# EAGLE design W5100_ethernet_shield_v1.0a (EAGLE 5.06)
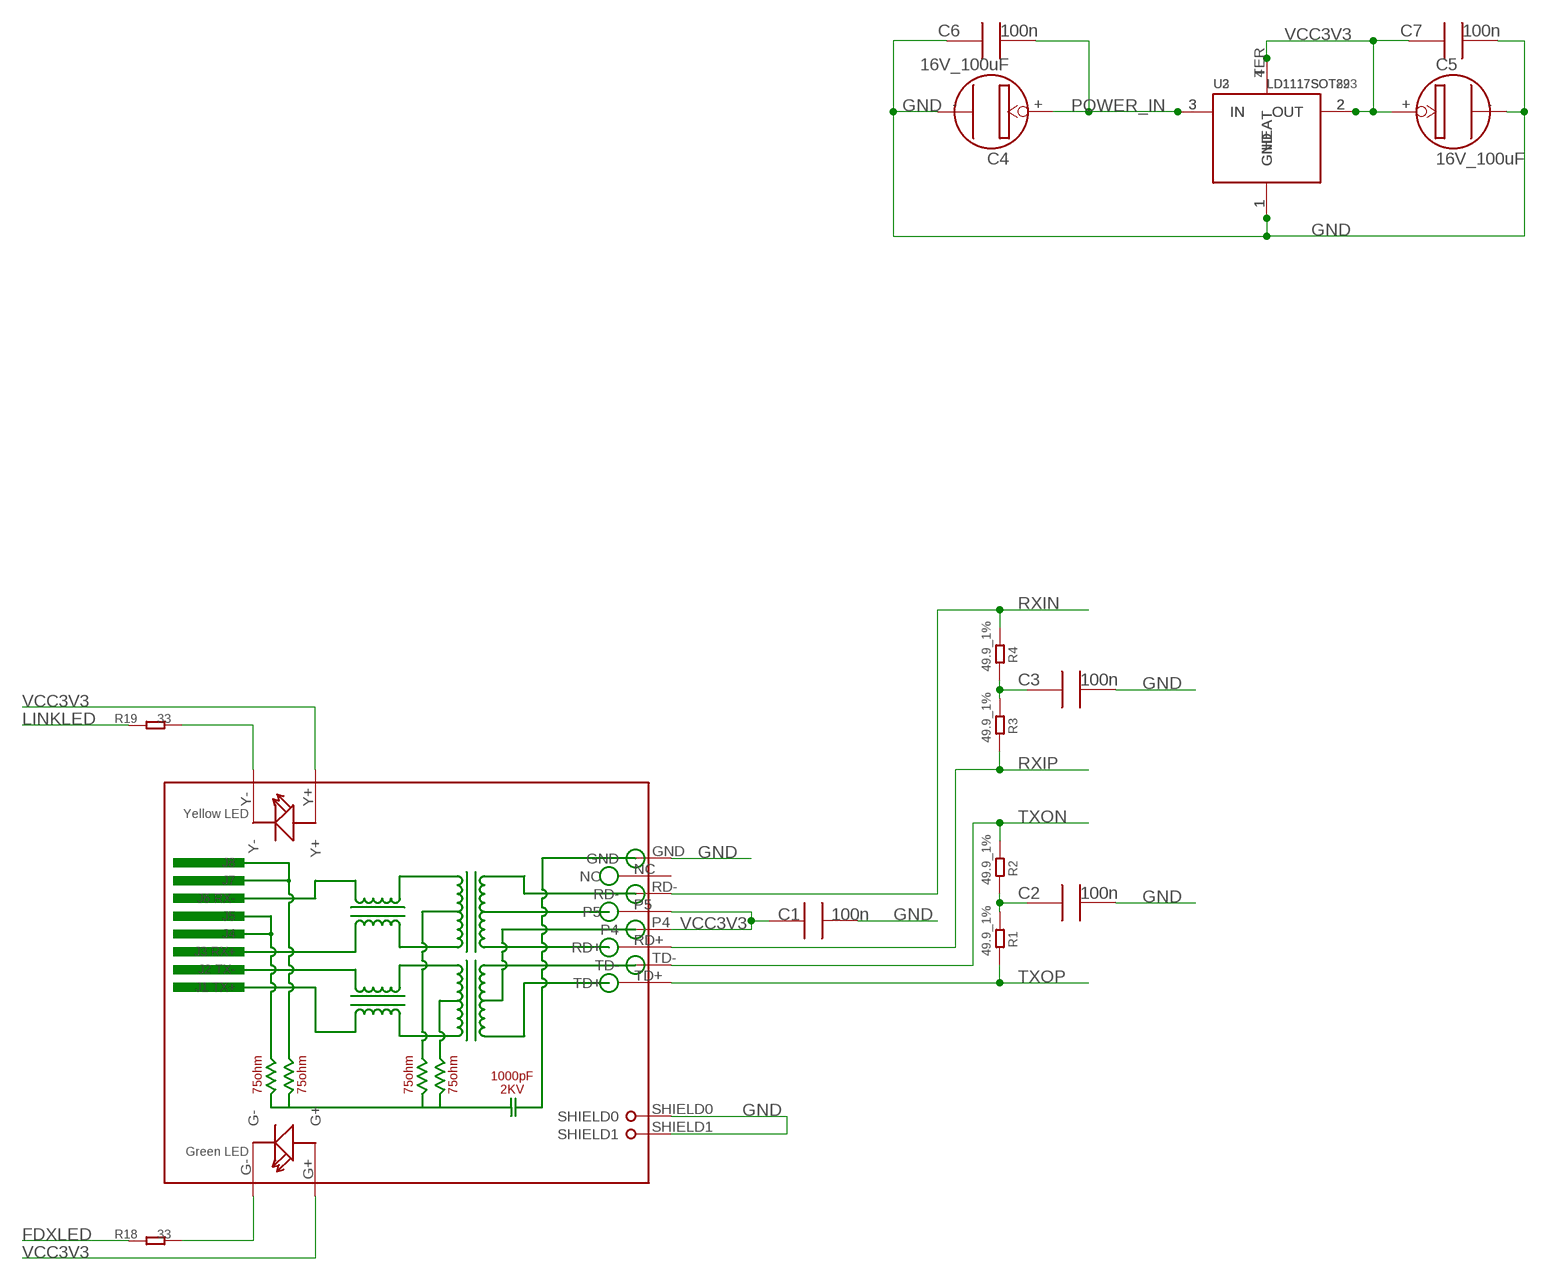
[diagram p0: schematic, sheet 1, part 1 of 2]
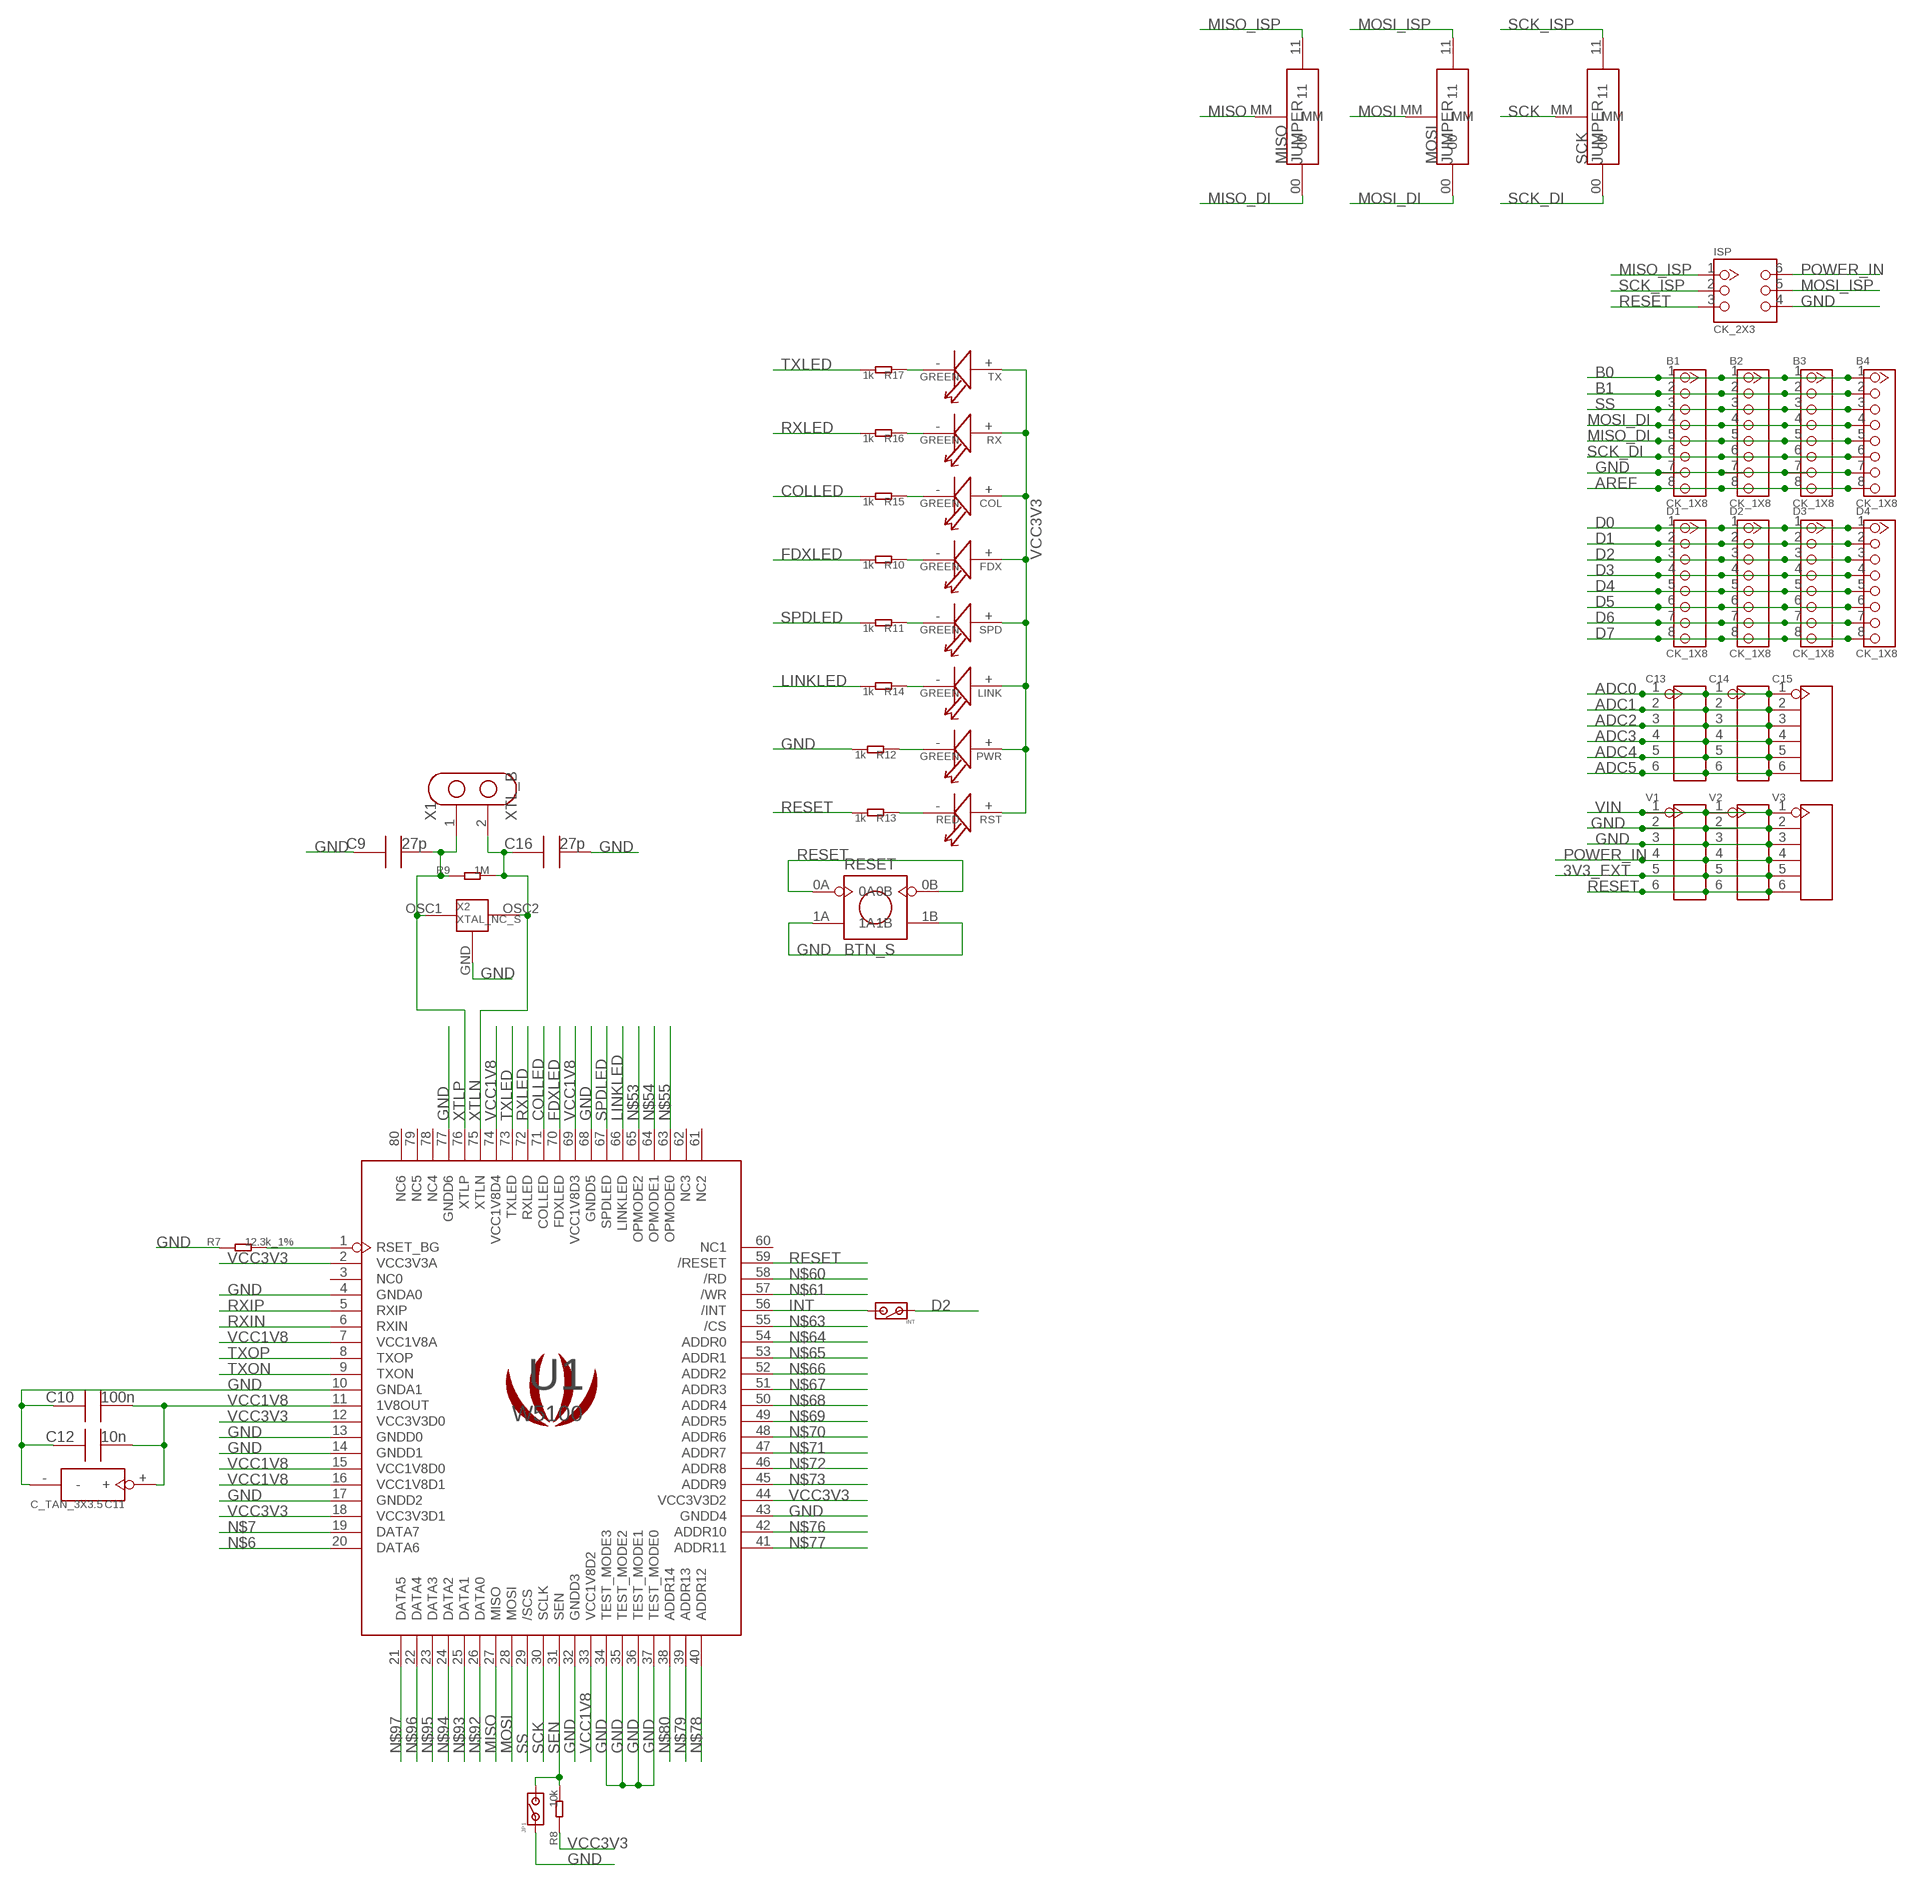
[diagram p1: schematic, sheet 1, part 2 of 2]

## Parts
B1  CK_1X8  CK_1X8DD  [CK_1X8]
B2  CK_1X8  CK_1X8DD  [CK_1X8]
B3  CK_1X8  CK_1X8DD  [CK_1X8]
B4  CK_1X8  CK_1X8DD  [CK_1X8]
C1  100n  C0603  [0603]
C2  100n  C0603  [0603]
C3  100n  C0603  [0603]
C4  16V_100uF  PANASONIC_D260  [SANYO-OSCON_SMD_C6]
C5  16V_100uF  PANASONIC_D260  [SANYO-OSCON_SMD_C6]
C6  100n  C0603  [0603]
C7  100n  C0603  [0603]
C9  27p  C0603  [0603]
C10  100n  C0603  [0603]
C11  C_TAN_3X3.5  [C_TAN_3X3.5]
C12  10n  C0603  [0603]
C13  CK_16  [CK_1*6]
C14  CK_16  [CK_1*6]
C15  CK_16  [CK_1*6]
C16  27p  C0603  [0603]
COL  GREEN  LED0805  [LED0805]
D1  CK_1X8  CK_1X8DD  [CK_1X8]
D2  CK_1X8  CK_1X8DD  [CK_1X8]
D3  CK_1X8  CK_1X8DD  [CK_1X8]
D4  CK_1X8  CK_1X8DD  [CK_1X8]
FDX  GREEN  LED0805  [LED0805]
INT  JP_SW  [JP_SW]
ISP  CK_2X3  [CK_2X3_THIN]
JP1  JP_SW  [JP_SW]
LINK  GREEN  LED0805  [LED0805]
LOGO1  LOGO_COPPER200X166  [LOGO_COPPER]
MISO  JUMPER  [JUMPER]
MOSI  JUMPER  [JUMPER]
PWR  GREEN  LED0805  [LED0805]
R1  49.9_1%  R0603  [0603]
R2  49.9_1%  R0603  [0603]
R3  49.9_1%  R0603  [0603]
R4  49.9_1%  R0603  [0603]
R7  12.3k_1%  R0603  [0603]
R8  10k  R0603  [0603]
R9  1M  R0603  [0603]
R10  1k  R0603  [0603]
R11  1k  R0603  [0603]
R12  1k  R0603  [0603]
R13  1k  R0603  [0603]
R14  1k  R0603  [0603]
R15  1k  R0603  [0603]
R16  1k  R0603  [0603]
R17  1k  R0603  [0603]
R18  33  R0603  [0603]
R19  33  R0603  [0603]
RESET  BTN_S  [BTN_S]
RJ1  HR911105A  [HR911105A]
RST  RED  LED0805  [LED0805]
RX  GREEN  LED0805  [LED0805]
SCK  JUMPER  [JUMPER]
SPD  GREEN  LED0805  [LED0805]
TX  GREEN  LED0805  [LED0805]
U1  W5100  [SQFP80]
U2  LD1117SOT89  [SOT89]
U3  LD1117SOT223  [SOT223]
V1  CK_16  [CK_1*6]
V2  CK_16  [CK_1*6]
V3  CK_16  [CK_1*6]
X1  XTL_B  [XTL_B]
X2  XTAL_NC_S  [XTAL_NC_S]

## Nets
3V3_EXT: V1.5 V2.5 V3.5
ADC0: C13.1 C14.1 C15.1
ADC1: C13.2 C14.2 C15.2
ADC2: C13.3 C14.3 C15.3
ADC3: C13.4 C14.4 C15.4
ADC4: C13.5 C14.5 C15.5
ADC5: C13.6 C14.6 C15.6
AREF: B1.8 B2.8 B3.8 B4.8
B0: B1.1 B2.1 B3.1 B4.1
B1: B1.2 B2.2 B3.2 B4.2
COLLED: R15.2 U1.71(COLLED)
D0: D1.1 D2.1 D3.1 D4.1
D1: D1.2 D2.2 D3.2 D4.2
D2: D1.3 D2.3 D3.3 D4.3 INT.1
D3: D1.4 D2.4 D3.4 D4.4
D4: D1.5 D2.5 D3.5 D4.5
D5: D1.6 D2.6 D3.6 D4.6
D6: D1.7 D2.7 D3.7 D4.7
D7: D1.8 D2.8 D3.8 D4.8
FDXLED: R10.2 R18.1 U1.70(FDXLED)
GND [power]: B1.7 B2.7 B3.7 B4.7 C1.2 C2.2 C3.2 C4.- C5.- C6.1 C7.2 C9.1 C10.1 C11.- C12.1 C16.2 ISP.4 JP1.1 R7.1 R12.2 RESET.1A RESET.1B RJ1.GND RJ1.SHIELD0 RJ1.SHIELD1 U1.4(GNDA0) U1.10(GNDA1) U1.13(GNDD0) U1.14(GNDD1) U1.17(GNDD2) U1.32(GNDD3) U1.34(TEST_MODE3) U1.35(TEST_MODE2) U1.36(TEST_MODE1) U1.37(TEST_MODE0) U1.43(GNDD4) U1.68(GNDD5) U1.77(GNDD6) U2.1(GND) U3.1(GND) V1.2 V1.3 V2.2 V2.3 V3.2 V3.3 X2.GND
INT: INT.2 U1.56(/INT)
LINKLED: R14.2 R19.1 U1.66(LINKLED)
MISO: MISO.MM U1.27(MISO)
MISO_DI: B1.5 B2.5 B3.5 B4.5 MISO.00
MISO_ISP: ISP.1 MISO.11
MOSI: MOSI.MM U1.28(MOSI)
MOSI_DI: B1.4 B2.4 B3.4 B4.4 MOSI.00
MOSI_ISP: ISP.5 MOSI.11
N$1: C2.1 R1.1 R2.2
N$2: R19.2 RJ1.Y-
N$3: C3.1 R3.1 R4.2
N$4: R18.2 RJ1.G-
N$5: PWR.- R12.1
N$6: U1.20(DATA6)
N$7: U1.19(DATA7)
N$13: R13.1 RST.-
N$18: FDX.- R10.1
N$24: R11.1 SPD.-
N$27: LINK.- R14.1
N$31: COL.- R15.1
N$35: R16.1 RX.-
N$38: R7.2 U1.1(RSET_BG)
N$39: R17.1 TX.-
N$53: U1.65(OPMODE2)
N$54: U1.64(OPMODE1)
N$55: U1.63(OPMODE0)
N$60: U1.58(/RD)
N$61: U1.57(/WR)
N$63: U1.55(/CS)
N$64: U1.54(ADDR0)
N$65: U1.53(ADDR1)
N$66: U1.52(ADDR2)
N$67: U1.51(ADDR3)
N$68: U1.50(ADDR4)
N$69: U1.49(ADDR5)
N$70: U1.48(ADDR6)
N$71: U1.47(ADDR7)
N$72: U1.46(ADDR8)
N$73: U1.45(ADDR9)
N$76: U1.42(ADDR10)
N$77: U1.41(ADDR11)
N$78: U1.40(ADDR12)
N$79: U1.39(ADDR13)
N$80: U1.38(ADDR14)
N$92: U1.26(DATA0)
N$93: U1.25(DATA1)
N$94: U1.24(DATA2)
N$95: U1.23(DATA3)
N$96: U1.22(DATA4)
N$97: U1.21(DATA5)
POWER_IN: C4.+ C6.2 ISP.6 U2.3(IN) U3.3(IN) V1.4 V2.4 V3.4
RESET: ISP.3 R13.2 RESET.0A RESET.0B U1.59(/RESET) V1.6 V2.6 V3.6
RXIN: R4.1 RJ1.RD- U1.6(RXIN)
RXIP: R3.2 RJ1.RD+ U1.5(RXIP)
RXLED: R16.2 U1.72(RXLED)
SCK: SCK.MM U1.30(SCLK)
SCK_DI: B1.6 B2.6 B3.6 B4.6 SCK.00
SCK_ISP: ISP.2 SCK.11
SEN: JP1.2 R8.2 U1.31(SEN)
SPDLED: R11.2 U1.67(SPDLED)
SS: B1.3 B2.3 B3.3 B4.3 U1.29(/SCS)
TXLED: R17.2 U1.73(TXLED)
TXON: R2.1 RJ1.TD- U1.9(TXON)
TXOP: R1.2 RJ1.TD+ U1.8(TXOP)
VCC1V8: C10.2 C11.+ C12.2 U1.7(VCC1V8A) U1.11(1V8OUT) U1.15(VCC1V8D0) U1.16(VCC1V8D1) U1.33(VCC1V8D2) U1.69(VCC1V8D3) U1.74(VCC1V8D4)
VCC3V3: C1.1 C5.+ C7.1 COL.+ FDX.+ LINK.+ PWR.+ R8.1 RJ1.G+ RJ1.P4 RJ1.P5 RJ1.Y+ RST.+ RX.+ SPD.+ TX.+ U1.2(VCC3V3A) U1.12(VCC3V3D0) U1.18(VCC3V3D1) U1.44(VCC3V3D2) U2.2(OUT) U2.4(HEAT) U3.2(OUT) U3.TER(HEAT)
VIN: V1.1 V2.1 V3.1
XTLN: C16.1 R9.2 U1.75(XTLN) X1.2 X2.OSC2
XTLP: C9.2 R9.1 U1.76(XTLP) X1.1 X2.OSC1
Unconnected: RJ1.NC U1.3(NC0) U1.60(NC1) U1.61(NC2) U1.62(NC3) U1.78(NC4) U1.79(NC5) U1.80(NC6)

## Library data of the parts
B1-B4 D1-D4 = CONNECTER:CK_1X8
C1-C3 C6 C7 C9 C10 C12 C16 = CPT_SMD:C0603; C0603: 100N
C4 C5 = CPT_SMD:PANASONIC_D
C11 = CPT_SMD:C_TAN
C13-C15 V1-V3 = CONNECTER:CK_1*6
COL FDX LINK PWR RST RX SPD TX = CPT_SMD:LED0805
INT JP1 = CPT_SMD:JP_SW
ISP = CONNECTER:CK_2X3
LOGO1 = logo:LOGO_COPPER
MISO MOSI SCK = CPT_SMD:JUMPER
R1-R4 R7-R19 = CPT_SMD:R0603
RESET = CPT_SMD:BTN_S
RJ1 = CONNECTER:HR911105A
U1 = ICs_v54:W5100
U2 U3 = ICs_v54:LD1117
X1 = CPT_CJ:XTL_B
X2 = CPT_SMD:XTAL_NC_S

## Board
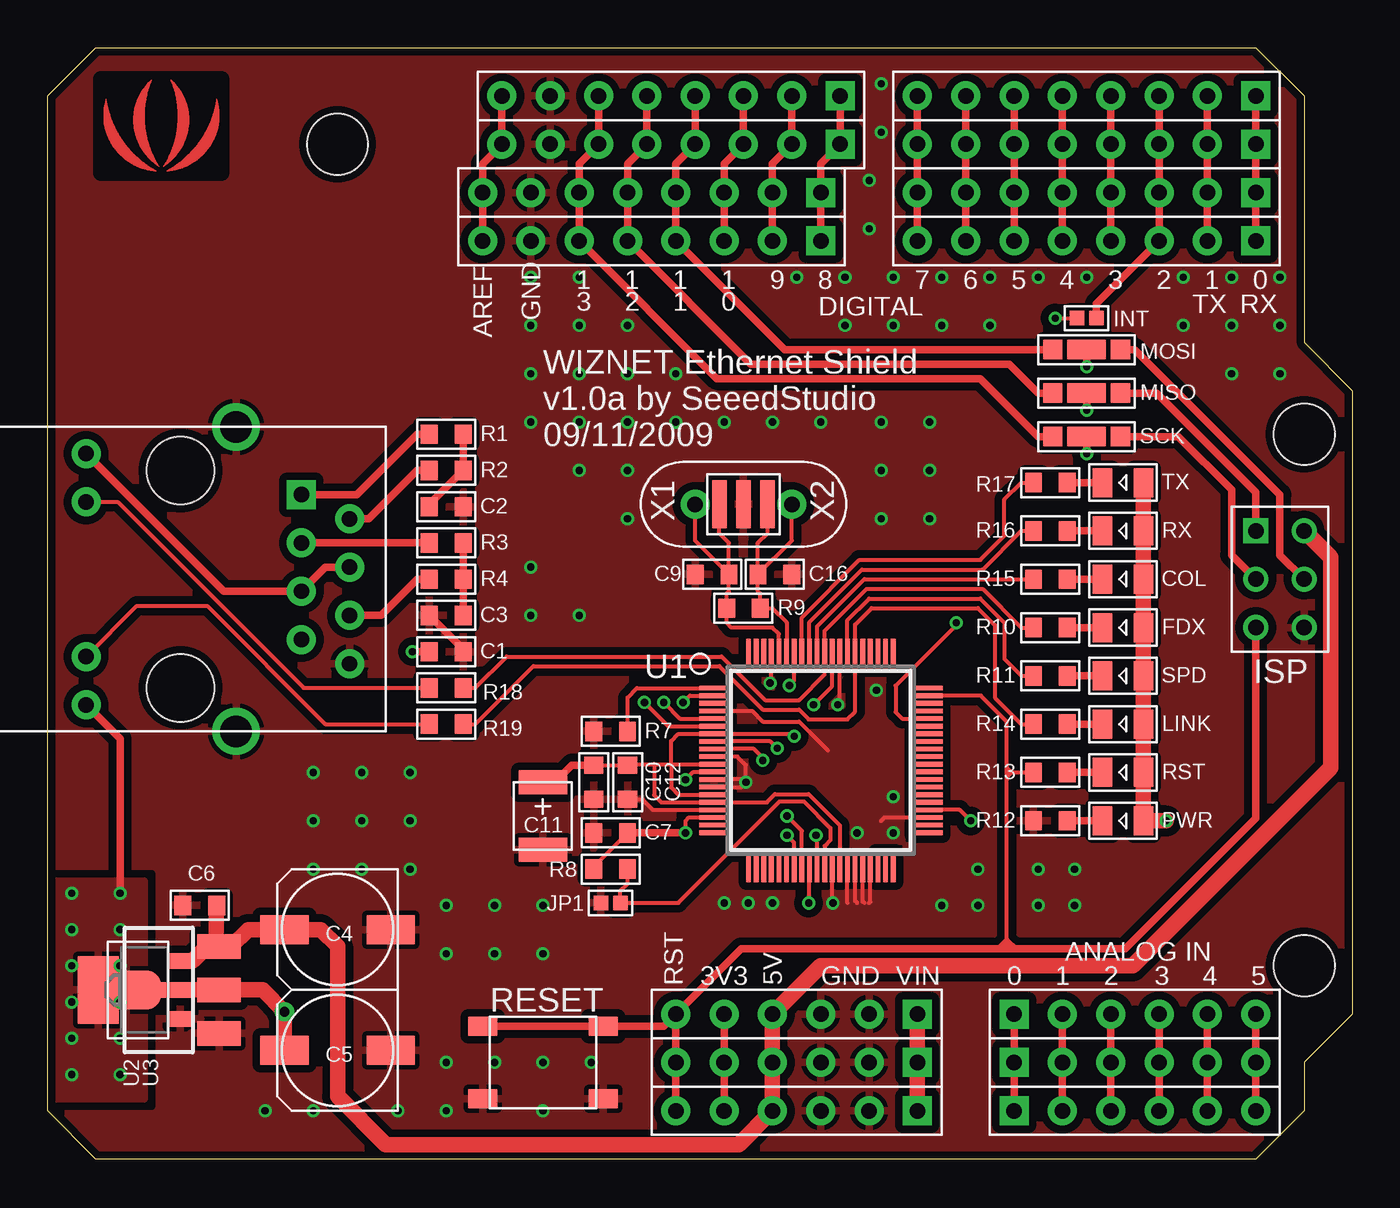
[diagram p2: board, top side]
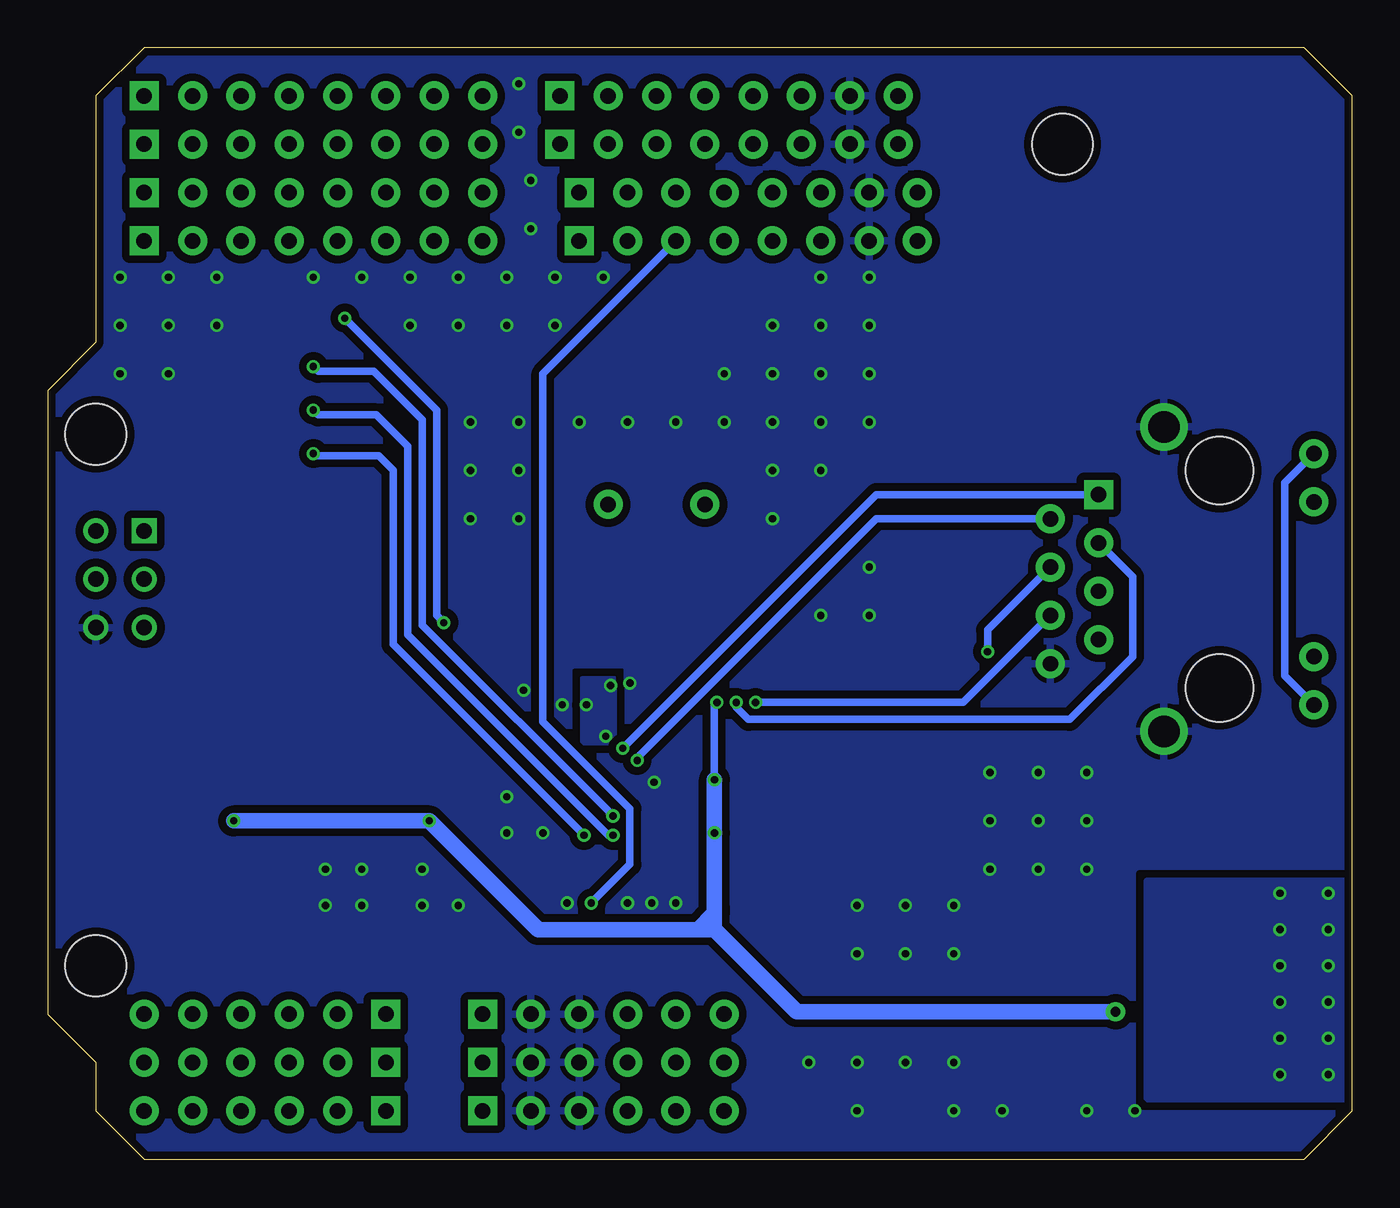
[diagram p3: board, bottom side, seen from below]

Size 68.58 x 58.42 mm. Coordinates in mm from the lower left corner, seen from the top.
Outline: 68.58,7.62 66.04,5.08 66.04,2.54 63.5,0 2.54,0 0,2.54 0,55.88 2.54,58.42 63.5,58.42 66.04,55.88 66.04,42.93 68.58,40.39 68.58,7.62
Copper layers (1*16): Top 0.035mm / dielectric 1.5mm / Bottom 0.035mm
Design rules "SeeedStudio_rule_no_angle *": minimum track width 0.0025mm, minimum drill 10mil, track to track 6mil, track to pad 6mil, pad to pad 5mil, via to via 6mil, smd to smd 0mil, copper to edge 10mil, drill to drill 10mil, minimum pad ring 10mil, minimum via ring 6mil, stop-mask expansion 2mil, vias tented up to drill 100mil, thermal gap 10mil
Holes 3.2 mm at 66.04,38.1 66.04,10.16 15.24,53.34
tRestrict: area 2.8,51.8 to 9.1,56.8; area 42,14.6 to 43.3,15.7

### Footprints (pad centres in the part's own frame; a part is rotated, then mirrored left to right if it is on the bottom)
CK_1X8 = drill 0.813 pad 1.524 square: 1 0,8.89 | drill 0.813 pad 1.524 round: 2 0,6.35; 3 0,3.81; 4 0,1.27; 5 0,-1.27; 6 0,-3.81; 7 0,-6.35; 8 0,-8.89
0603 = smd 0.889 x 1.016: 1 -0.889,0; 2 0.889,0
SANYO-OSCON_SMD_C6 = smd 2.54 x 1.524: + 2.794,0; - -2.794,0
C_TAN_3X3.5 = smd 2.54 x 1.27: + 0,1.778; - 0,-1.778
CK_1*6 = drill 0.813 pad 1.524 square: 1 0,6.35 | drill 0.813 pad 1.524 round: 2 0,3.81; 3 0,1.27; 4 0,-1.27; 5 0,-3.81; 6 0,-6.35
LED0805 = smd 1.016 x 1.524: + -1.077,0; - 1.077,0
JP_SW = smd 0.762 x 0.762: 1 0,0.508; 2 0,-0.508
CK_2X3_THIN = drill 0.813 pad 1.27 square: 1 -1.27,2.54 | drill 0.813 pad 1.27 round: 2 -1.27,0; 3 -1.27,-2.54; 4 1.27,-2.54; 5 1.27,0; 6 1.27,2.54
JUMPER = smd 1.016 x 1.016: 00 -1.778,0; 11 1.778,0 | smd 2.032 x 1.016: MM 0,0
BTN_S = smd 1.524 x 1.016: 0A -3.175,1.905; 0B 3.175,1.905; 1A -3.175,-1.905; 1B 3.175,-1.905
HR911105A = drill 0.813 pad 1.524 round: G+ 4.953,-6.604; G- 4.953,-4.064; GND -8.89,4.445; NC -6.35,3.175; P4 -8.89,-0.635; P5 -6.35,0.635; RD+ -6.35,-1.905; RD- -8.89,1.905; TD- -8.89,-3.175; Y+ 4.953,6.604; Y- 4.953,4.064 | drill 1.651 pad 2.159 round: SHIELD0 -2.921,8.001; SHIELD1 -2.921,-8.001 | drill 0.813 pad 1.524 square: TD+ -6.35,-4.445 | hole 3.556: 0,-5.715; 0,5.715
SQFP80 = smd 1.6 x 0.25: 1 -5.6,3.8; 2 -5.6,3.4; 3 -5.6,3; 4 -5.6,2.6; 5 -5.6,2.2; 6 -5.6,1.8; 7 -5.6,1.4; 8 -5.6,1; 9 -5.6,0.6; 10 -5.6,0.2; 11 -5.6,-0.2; 12 -5.6,-0.6; 13 -5.6,-1; 14 -5.6,-1.4; 15 -5.6,-1.8; 16 -5.6,-2.2; 17 -5.6,-2.6; 18 -5.6,-3; 19 -5.6,-3.4; 20 -5.6,-3.8; 41 5.6,-3.8; 42 5.6,-3.4; 43 5.6,-3; 44 5.6,-2.6; 45 5.6,-2.2; 46 5.6,-1.8; 47 5.6,-1.4; 48 5.6,-1; 49 5.6,-0.6; 50 5.6,-0.2; 51 5.6,0.2; 52 5.6,0.6; 53 5.6,1; 54 5.6,1.4; 55 5.6,1.8; 56 5.6,2.2; 57 5.6,2.6; 58 5.6,3; 59 5.6,3.4; 60 5.6,3.8 | smd 0.25 x 1.6: 21 -3.8,-5.6; 22 -3.4,-5.6; 23 -3,-5.6; 24 -2.6,-5.6; 25 -2.2,-5.6; 26 -1.8,-5.6; 27 -1.4,-5.6; 28 -1,-5.6; 29 -0.6,-5.6; 30 -0.2,-5.6; 31 0.2,-5.6; 32 0.6,-5.6; 33 1,-5.6; 34 1.4,-5.6; 35 1.8,-5.6; 36 2.2,-5.6; 37 2.6,-5.6; 38 3,-5.6; 39 3.4,-5.6; 40 3.8,-5.6; 61 3.8,5.6; 62 3.4,5.6; 63 3,5.6; 64 2.6,5.6; 65 2.2,5.6; 66 1.8,5.6; 67 1.4,5.6; 68 1,5.6; 69 0.6,5.6; 70 0.2,5.6; 71 -0.2,5.6; 72 -0.6,5.6; 73 -1,5.6; 74 -1.4,5.6; 75 -1.8,5.6; 76 -2.2,5.6; 77 -2.6,5.6; 78 -3,5.6; 79 -3.4,5.6; 80 -3.8,5.6
SOT89 = smd 0.8 x 1.4: 1 -1.524,-1.905; 3 1.524,-1.905 | smd 0.8 x 1.9: 2 0,-1.651 | smd 2.032 x 3.65: 4 0,0.94
SOT223 = smd 1.27 x 2.286: 1 -2.286,-3.175; 2 0,-3.175; 3 2.286,-3.175 | smd 3.556 x 2.159: TER 0,3.175
XTL_B = drill 0.813 pad 1.524 round: 1 0,2.54; 2 0,-2.54
XTAL_NC_S = smd 0.762 x 2.54: GND 0,0; OSC1 -1.27,0; OSC2 1.27,0

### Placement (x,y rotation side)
B1  32.77,55.88 270 top
B2  32.77,53.34 270 top
B3  31.75,50.8 270 top
B4  31.75,48.26 270 top
C1  20.95,26.67 0 top
C2  20.95,34.29 0 top
C3  20.95,28.57 180 top
C4  15.24,12.06 180 top
C5  15.24,5.71 180 top
C6  8,13.34 0 top
C7  29.59,17.14 180 top
C9  34.92,30.73 0 top
C10  28.7,19.81 90 top
C11  26.04,18.03 0 top
C12  30.48,19.81 90 top
C13  57.15,7.62 90 top
C14  57.15,5.08 90 top
C15  57.15,2.54 90 top
C16  38.23,30.73 0 top
COL  56.52,30.48 180 top
D1  54.61,55.88 270 top
D2  54.61,53.34 270 top
D3  54.61,50.8 270 top
D4  54.61,48.26 270 top
FDX  56.52,27.94 180 top
INT  54.61,44.2 270 top
ISP  64.77,30.48 0 top
JP1  29.59,13.46 90 top
LINK  56.52,22.86 180 top
LOGO1  5.97,53.59 0 top
MISO  54.61,40.26 0 top
MOSI  54.61,42.55 0 top
PWR  56.52,17.78 180 top
R1  20.95,38.1 180 top
R2  20.95,36.2 0 top
R3  20.95,32.38 180 top
R4  20.95,30.48 0 top
R7  29.59,22.48 0 top
R8  29.59,15.24 0 top
R9  36.58,28.96 0 top
R10  52.7,27.94 180 top
R11  52.7,25.4 180 top
R12  52.7,17.78 180 top
R13  52.7,20.32 180 top
R14  52.7,22.86 180 top
R15  52.7,30.48 180 top
R16  52.7,33.02 180 top
R17  52.7,35.56 180 top
R18  20.95,24.77 180 top
R19  20.95,22.86 180 top
RESET  26.04,5.08 0 top
RJ1  6.99,30.48 180 top
RST  56.52,20.32 180 top
RX  56.52,33.02 180 top
SCK  54.61,37.97 0 top
SPD  56.52,25.4 180 top
TX  56.52,35.56 180 top
U1  40.64,20.95 0 top
U2  5.08,8.89 90 top
U3  5.84,8.89 90 top
V1  39.37,7.62 270 top
V2  39.37,5.08 270 top
V3  39.37,2.54 270 top
X1  36.58,34.42 90 top
X2  36.58,34.42 0 top

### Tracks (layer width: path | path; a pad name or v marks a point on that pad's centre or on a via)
3V3_EXT
  Top 0.406: V1.5 V2.5 V3.5
ADC0
  Top 0.406: C15.1 C14.1 C13.1
ADC1
  Top 0.406: C13.2 C14.2 C15.2
ADC2
  Top 0.406: C15.3 C14.3 C13.3
ADC3
  Top 0.406: C13.4 C14.4 C15.4
ADC4
  Top 0.406: C15.5 C14.5 C13.5
ADC5
  Top 0.406: C13.6 C14.6 C15.6
AREF
  Top 0.406: B4.8 B3.8 22.86,52.32 B2.8 B1.8
B0
  Top 0.406: B4.1 B3.1 40.64,52.32 B2.1 B1.1
B1
  Top 0.406: B1.2 B2.2 38.1,52.32 B3.2 B4.2
COLLED
  Top 0.203: U1.71 40.44,27.99 42.93,30.48 R15.2
D0
  Top 0.406: D4.1 D3.1 D2.1 D1.1
D1
  Top 0.406: D1.2 D2.2 D3.2 D4.2
D2
  Top 0.406: D1.3 D2.3 D3.3 D4.3 55.12,44.96 INT.1
D3
  Top 0.406: D1.4 D2.4 D3.4 D4.4
D4
  Top 0.406: D4.5 D3.5 D2.5 D1.5
D5
  Top 0.406: D1.6 D2.6 D3.6 D4.6
D6
  Top 0.406: D4.7 D3.7 D2.7 D1.7
D7
  Top 0.406: D1.8 D2.8 D3.8 D4.8
FDXLED
  Top 0.203: R10.2 51.18,27.94 49.15,29.97 43.05,29.97 40.84,27.76 U1.70 40.84,25.47 39.5,24.13 37.72,24.13 35.43,26.42 24.13,26.42 22.48,24.77 R18.1
GND  (via drill 0.38)
  Top 0.203: U1.32 41.24,13.5 v41.27,13.46 | U1.4 37.02,23.55 37.59,22.99 39.5,22.99 41.02,21.46 | U1.77 38.04,25.09 v37.97,25.02 | U1.68 41.64,23.99 v41.53,23.88 | U1.43 43.99,17.95 43.81,17.78 | U1.10 36.25,21.16 36.7,20.7 v36.7,19.81 | U1.13 36.56,19.95 v36.7,19.81 | U1.14 36.45,19.55 v36.7,19.81 | U1.37 43.24,13.52 43.18,13.46 | U1.36 42.84,13.55 42.93,13.46 | U1.35 42.44,13.57 42.55,13.46 | U1.34 42.04,13.46 | U1.17 31.81,18.36 31.24,18.92 C12.1
  Top 0.406: C1.2 21.84,26.8 C3.2
  other vias: 52.07,15.24 53.98,15.24 43.56,24.64 52.07,13.34 53.98,13.34 48.9,15.24 48.9,13.34 46.99,13.34 59.69,46.35 62.23,46.35 49.53,46.35 46.99,46.35 54.61,46.35 52.07,46.35 59.69,43.81 62.23,43.81 46.99,43.81 49.53,43.81 44.45,43.81 44.45,46.35 41.91,46.35 41.91,43.81 43.18,48.9 43.18,51.44 43.81,53.98 43.81,56.52 39.37,46.35 62.23,41.27 64.77,46.35 64.77,43.81 64.77,41.27 27.94,46.35 25.4,46.35 27.94,43.81 27.94,41.27 30.48,41.27 30.48,43.81 25.4,43.81 25.4,41.27 25.4,38.73 27.94,38.73 30.48,38.73 33.02,38.73 33.02,41.27 35.56,38.73 38.1,38.73 40.64,38.73 27.94,36.2 30.48,36.2 30.48,33.66 43.81,38.73 43.81,36.2 43.81,33.66 46.35,33.66 46.35,36.2 46.35,38.73 19.05,17.78 19.05,15.24 16.51,17.78 16.51,15.24 13.97,15.24 13.97,17.78 26.04,13.34 23.5,13.34 20.95,13.34 20.95,10.79 23.5,10.79 26.04,10.79 28.57,5.08 26.04,5.08 23.5,5.08 20.95,5.08 20.95,2.54 18.41,2.54 13.97,2.54 11.43,2.54 26.04,2.54 38.1,13.46 36.83,13.46 35.56,13.46 25.4,31.11 25.4,28.57 27.94,28.57 13.97,20.32 16.51,20.32 19.05,20.32 44.45,19.05 44.45,17.14 42.55,17.14
  pour Bottom (isolate 0.406, rank 6): 0,55.88 2.54,58.42 63.5,58.42 66.04,55.88 66.04,42.93 68.58,40.39 68.58,7.62 66.04,5.08 66.04,2.54 63.5,0 2.54,0 0,2.54
  pour Top (isolate 0.406, rank 6): 0,55.88 2.54,58.42 63.5,58.42 66.04,55.88 66.04,42.93 68.58,40.39 68.58,7.62 66.04,5.08 66.04,2.54 63.5,0 2.54,0 0,2.54
  pour Top: -13.97,51.44 -12.06,51.44 -12.06,50.16 -13.97,50.16
INT  (via drill 0.38)
  Top 0.203: v52.96,44.2 INT.2 | U1.56 44.92,23.16 44.58,23.5 44.58,24.89 47.75,28.07 v47.75,28.19
  Bottom 0.406: v52.96,44.2 48.13,39.37 48.13,28.57 v47.75,28.19
LINKLED
  Top 0.203: R14.2 51.18,22.86 49.78,24.26 49.78,28.07 48.9,28.96 43.31,28.96 42.44,28.09 U1.66 42.44,23.52 42.04,23.11 40.01,23.11 39.5,23.62 37.59,23.62 35.31,25.91 25.53,25.91 22.48,22.86 R19.1
MISO  (via drill 0.38)
  Top 0.203: U1.27 39.24,16.64 v38.86,17.02
  Top 0.406: v54.61,39.37 MISO.MM
  Bottom 0.406: v54.61,39.37 54.36,39.12 51.31,39.12 49.66,37.47 49.66,27.56 39.12,17.02 v38.86,17.02
MISO_DI
  Top 0.406: B1.5 B2.5 30.48,52.32 B3.5 B4.5 36.96,41.78 50.55,41.78 52.07,40.26 MISO.00
MISO_ISP
  Top 0.406: ISP.1 63.5,35.05 58.29,40.26 MISO.11
MOSI  (via drill 0.38)
  Top 0.203: U1.28 39.64,17.26 v38.86,18.03
  Top 0.406: v54.61,41.66 MOSI.MM
  Bottom 0.406: v54.61,41.66 54.36,41.4 51.44,41.4 48.9,38.86 48.9,28.07 v38.86,18.03
MOSI_DI
  Top 0.406: B1.4 B2.4 33.02,52.32 B3.4 B4.4 38.73,42.55 MOSI.00
MOSI_ISP
  Top 0.406: ISP.5 64.77,31.75 64.77,34.92 57.15,42.55 MOSI.11
N$1
  Top 0.406: R1.1 R2.2 20.07,34.42 C2.1
N$2
  Top 0.203: R19.2 14.61,22.86 8.38,29.08 4.7,29.08 RJ1.Y-
N$3
  Top 0.406: C3.1 R4.2 R3.1
N$4
  Top 0.203: R18.2 13.46,24.77 3.68,34.54 RJ1.G-
N$5
  Top 0.406: R12.1 PWR.-
N$13
  Top 0.406: RST.- R13.1
N$18
  Top 0.406: FDX.- R10.1
N$24
  Top 0.406: SPD.- R11.1
N$27
  Top 0.406: LINK.- R14.1
N$31
  Top 0.406: COL.- R15.1
N$35
  Top 0.406: RX.- R16.1
N$38
  Top 0.203: U1.1 30.98,24.75 30.48,24.26 R7.2
N$39
  Top 0.406: TX.- R17.1
POWER_IN
  Top 0.813: ISP.6 67.44,31.62 67.44,20.57 57.02,10.16 40.64,10.16 V1.4 V2.4 V3.4 36.32,0.76 17.78,0.76 15.24,3.3 15.24,11.18 14.35,12.06 C4.+ 10.54,12.06 9.65,11.18 U3.3 | U2.3 7.62,10.41 8.38,11.18 U3.3 | C6.2 8.85,11.34 U3.3
RESET
  Top 0.203: U1.59 49.05,24.36 50.42,22.99 50.42,20.32 | 50.42,11.05 49.91,11.05 | 49.91,11.05 49.66,11.05 | 49.91,11.05 50.42,11.56 | 50.42,11.05 50.42,11.56 | 50.42,11.05 50.93,11.05 | 50.93,11.05 51.05,11.05 | 50.42,11.56 50.93,11.05 | 50.42,11.56 50.42,11.43 | 50.42,11.43 50.67,11.18 50.29,11.18 50.29,11.3 50.42,11.43 | 50.42,11.43 50.42,20.32 | 50.42,20.32 50.42,20.57 | 50.42,20.57 50.42,20.7 | 50.42,20.57 50.67,20.32 | 50.42,20.32 50.67,20.32 | 50.42,20.32 50.42,20.07 | 50.42,20.07 50.42,19.94 | 50.67,20.32 50.42,20.07 | 50.67,20.32 R13.2
  Top 0.406: V3.6 V2.6 V1.6 | ISP.3 63.5,17.91 56.64,11.05 50.42,11.05 36.45,11.05 V1.6 | V1.6 32.38,6.99 RESET.0B RESET.0A
RXIN  (via drill 0.38)
  Top 0.203: U1.6 32.62,22.75 v31.37,24
  Top 0.406: RJ1.RD- 17.53,28.57 19.43,30.48 R4.1
  Bottom 0.406: v31.37,24 20.45,24 RJ1.RD-
RXIP  (via drill 0.38)
  Top 0.203: U1.5 33.23,23.16 v32.38,24
  Top 0.406: RJ1.RD+ R3.2
  Bottom 0.406: v32.38,24 32.38,23.75 31.75,23.11 14.86,23.11 11.56,26.42 11.56,30.61 RJ1.RD+
RXLED
  Top 0.203: U1.72 40.04,28.23 42.8,30.99 49.15,30.99 51.18,33.02 R16.2
SCK  (via drill 0.38)
  Top 0.203: U1.30 40.44,16.96 v40.39,17.02
  Top 0.406: v54.61,37.08 SCK.MM
  Bottom 0.406: v54.61,37.08 54.48,36.96 51.18,36.96 50.42,36.2 50.42,27.05 v40.39,17.02
SCK_DI
  Top 0.406: B1.6 B2.6 27.94,52.32 B3.6 B4.6 35.18,41.02 49.02,41.02 52.07,37.97 SCK.00
SCK_ISP
  Top 0.406: ISP.2 62.23,31.75 62.23,35.18 59.44,37.97 SCK.11
SEN
  Top 0.203: U1.31 40.84,16.46 41.15,16.76 41.15,17.4 39.75,18.8 38.48,18.8 33.15,13.46 JP1.2 30.1,14.1 30.48,14.48 R8.2
SPDLED
  Top 0.203: R11.2 51.18,25.4 50.29,26.29 50.29,28.19 49.02,29.46 43.18,29.46 42.04,28.32 U1.67
SS  (via drill 0.38)
  Top 0.203: U1.29 40.04,13.5 v40.01,13.46
  Top 0.406: B4.3 B3.3 35.56,52.32 B2.3 B1.3
  Bottom 0.406: v40.01,13.46 37.97,15.49 37.97,18.41 42.55,22.99 42.55,41.27 B4.3
TXLED
  Top 0.203: U1.73 39.64,28.46 42.67,31.5 49.02,31.5 50.29,32.77 50.29,34.67 51.18,35.56 R17.2
TXON  (via drill 0.38)
  Top 0.203: U1.9 37.12,21.55 37.59,21.08 v37.59,20.95
  Top 0.406: RJ1.TD- 16.89,33.66 19.43,36.2 R2.1
  Bottom 0.406: RJ1.TD- 25.02,33.66 37.59,21.08 v37.59,20.95
TXOP  (via drill 0.38)
  Top 0.203: U1.8 37.99,21.95 v38.35,21.59
  Top 0.406: RJ1.TD+ 16.26,34.92 19.43,38.1 R1.2
  Bottom 0.406: v38.35,21.59 25.02,34.92 RJ1.TD+
VCC1V8  (via drill 0.38)
  Top 0.203: 31.88,20.75 30.57,20.75 C12.2 C10.2 | 31.88,20.75 32.77,20.75 | 32.77,20.75 U1.11 | 31.88,20.75 31.88,19.14 32.26,18.75 U1.16 37.8,18.75 38.23,19.18 40.01,19.18 41.64,17.54 U1.33 | 32.77,20.75 32.77,19.54 33.15,19.16 U1.15 | 32.77,20.75 32.77,21.97 33.15,22.36 U1.7 39.11,22.36 v39.24,22.23 | U1.74 39.24,25.14 v38.99,24.89 | U1.69 41.24,24.86 v40.26,23.88
  Top 0.406: C10.2 27.56,20.7 26.67,19.81 C11.+
  pour Bottom (isolate 0.406): 38.73,25.27 40.51,25.27 40.51,21.84 38.73,21.84
VCC3V3  (via drill 0.38, 0.51 pad 1.02)
  Top 0.203: U1.2 33.75,24.36 v33.4,24 | U1.12 33.94,20.36 v33.53,19.94 | U1.44 47.94,18.36 v48.51,17.78 | R8.1 28.7,15.37 C7.1 | U1.18 33.7,17.95 33.53,17.78 v33.53,17.14
  Top 0.406: U2.4 4.45,8.89 | RJ1.P4 14.61,31.11 RJ1.P5 9.27,29.84 RJ1.G+ | v19.18,26.67 C1.1 | RJ1.Y+ 3.81,22.1 v3.81,13.97 | v33.53,17.14 C7.1
  Top 0.813: TX.+ RX.+ COL.+ FDX.+ SPD.+ LINK.+ RST.+ PWR.+ v58.8,17.78 | 4.45,8.89 U2.2 U3.2 11.3,8.89 v12.45,7.75 C5.+ | U3.TER U2.4
  Bottom 0.406: v33.4,24 33.53,23.88 v33.53,19.94 | RJ1.P4 19.18,27.81 v19.18,26.67 | RJ1.Y+ 3.56,25.4 3.56,35.56 RJ1.G+
  Bottom 0.813: v33.53,19.94 v33.53,17.14 33.53,13.21 | 33.53,12.06 34.29,12.06 | 33.53,12.06 34.42,12.06 | 34.42,12.06 42.8,12.06 v48.51,17.78 v58.8,17.78 | v12.45,7.75 29.21,7.75 33.91,12.45 33.78,12.45 33.53,12.19 | 33.53,12.19 33.53,13.21 | 33.53,12.19 33.53,12.06 | 33.53,13.21 33.53,12.95 34.42,12.06
  other vias: 1.27,13.97 1.27,12.06 3.81,12.06 3.81,10.16 1.27,10.16 1.27,8.26 3.81,8.26 1.27,6.35 3.81,6.35 3.81,4.45 1.27,4.45
  pour Top: -13.97,49.53 -12.06,49.53 -12.06,48.26 -13.97,48.26
  pour Top (isolate 0.406): 0,14.61 5.08,14.61 5.08,3.17 0,3.17
  pour Bottom (isolate 0.406): 0,14.61 10.79,14.61 10.79,3.17 0,3.17
VIN
  Top 0.813: V3.1 V2.1 V1.1
XTLN
  Top 0.203: U1.75 38.84,28.22 38.1,28.96 R9.2 37.47,29.72 37.34,29.84 C16.1 | X1.2 39.12,32.51 C16.1 | X2.OSC2 37.85,32.89 37.34,32.38 C16.1
XTLP
  Top 0.203: C9.2 35.81,29.84 35.69,29.72 R9.1 35.69,28.19 35.94,27.94 38.1,27.94 38.44,27.6 U1.76 | X1.1 34.04,32.51 C9.2 | X2.OSC1 35.31,32.89 35.81,32.38 C9.2

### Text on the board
Top: top layer
Bottom: bottom layer
Dimension: boardoutline
tPlace: silktop | 1 | 1 | 1 | 1 | 9 | 8 | 7 | 6 | 5 | 4 | 3 | 2 | 1 | 0 | 3 | 2 | 1 | 0 | TX | RX | GND | DIGITAL | AREF | WIZNET Ethernet Shield | v1.0a by SeeedStudio | 09/11/2009 | ANALOG IN | RST | 3V3 | 5V | GND | VIN | 0 | 1 | 2 | 3 | 4 | 5
bPlace: silkbottom
tStop: soldermask top
bStop: soldermask bottom
tCream: padmask top
bCream: padmask bottom
Drills: drill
